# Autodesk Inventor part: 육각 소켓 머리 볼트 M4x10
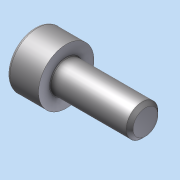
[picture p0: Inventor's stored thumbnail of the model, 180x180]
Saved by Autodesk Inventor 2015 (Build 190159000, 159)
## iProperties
Created: 2024-05
Part Number: 육각 소켓 머리 볼트 M4x10
Material: 일반
Document SubType Name: Modeling
Designer: Administrator
Density: 1 g/cm^3
Appearance: 기본값
Author: Administrator
Author: jhkim
Description: 6각머리 태핑 나사
Creation Date: 2024-05-07
Sending System: Autodesk Inventor 2025
Preprocessor: ST-DEVELOPER v20
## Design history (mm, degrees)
node "육각 소켓 머리 볼트 M4x101"
body "Solid1"
node "기준1"
